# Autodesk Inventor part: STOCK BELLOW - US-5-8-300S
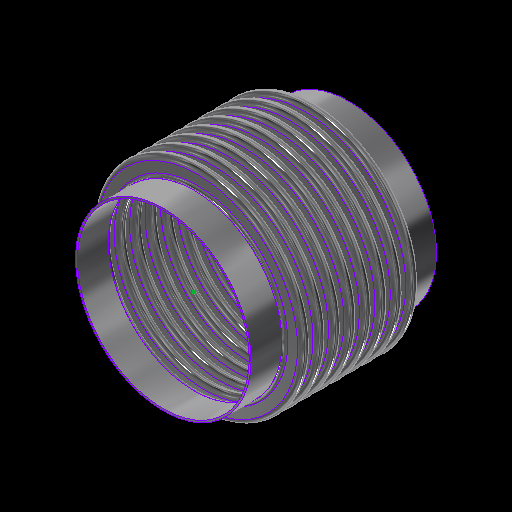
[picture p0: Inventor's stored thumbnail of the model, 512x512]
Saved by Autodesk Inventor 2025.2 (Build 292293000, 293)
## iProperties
Category: 22 GA (0.030 THICK)
RuleStatus: InUse
Created: 2024-01
Part Number: STOCK BELLOW - US-5-8-300S
Project: =STOCK BELLOWS: <Stock Number><SFILL>
Material: ASTM A240-304
Description: =STOCK BELLOWS: <Stock Number>, <SID_> I.D., <SOD_> O.D., <SPLY_> PLY, <Category>, <SNET_CONS> CONS.<PITCH_><STANGENT_> TANGENT<SFILL>
Document SubType Name: Sheet Metal
Designer: GS
Stock Number: U.S-5-8-300S
Surface Area: 3335.57 cm^2
Volume: 251.046 cm^3
Sheet Metal Rule: Default
Appearance: STAINLESS STEEL
Mass: 2022.75 g
Density: 8.05729 g/cm^3
THK: 0.036
ID: 3.500
OD: 4.250
CONS_: 2
PITCH: 0.500
TANGENT: 0.500
BELLOWS_UPSET: 0.000
d79: 1.000
d82: 1.000
d83: 26.000
d84: 24.000
d174: 8
d214: 8
STHK_: 0.030
SID_: 5.560
SOD_: 6.810
SPITCH_: 0.500
STANGENT__: 1.000
SBELLOWS_UPSET_: 0.000
SDIFF_TAN: 1.000
d252: 2
d275: 2
d287: 0.050
d289: 0.500
d290: 0.000
SOD_NECK: 5 11/16
PLY: 1
PSET: 4.178
PBAR: 1.035
COUNTER: 1.500
NET_TUBE: 3.071
CONS: 2
S_CONS: 0
NET_CONS: 2
ID_M: 88.90 mm
OD_M: 107.95 mm
THK_M: 0.91 mm
ID_U: 3.500 in
OD_U: 4.250 in
THK_U: 0.036 in
TANGENT2: 0.500
TAN_TO_TAN: 1.000 in
d80: 2.571
d81: 10
SID: 2.375
SCONS_: 8
SPITCH: 0.250
STANGENT_: 1.000
SBELLOWS_UPSET: 0.000
SNET_CONS: 8
SS_CONS: 0
SCONS: 8
d190: 8
d191: 1
d192: 1
d193: 8
d194: 0
SIZE: 5.00
PRESSURE: 300
d230: 8
STANGENT: 4.000
SPLY_: 2
d233: 8
d234: 0
d263: 2
d265: 1
d268: 2
d269: 0
d286: 2
d288: 1
d291: 2
d292: 0
SREROLL: 0.750
BLETP: 0.000 ul
PRES_Copy: 85
MATTABLE: 20 GA (0.036 THICK)
PART_NUMBER: U.S-5-8-300S
PITCH_: =, <SPITCH_> PITCH,
CFILL: .
SFILL: .
MESH: ,
COMP: 0.74
EXT: 0.37
LAT: 0.16
ANG: 573
ASR: 3217
LSR: 11536
ANSR: 268
PRES: 300
COMPM: 7.4
EXTM: 3.7
LATM: 1.60
ASRM: 563.393
PRESM: 20.684
LSRM: 2020.300
ANSRM: 46.935
TEMPMIN: 20
TEMPMAX: 800
TEMPMINM: -7
TEMPMAXM: 427
WEIGHTM: 2.023
WEIGHT: 4.459
Author: GS
Keywords: 20 GA (0.036 THICK)
Comments: =STOCK BELLOW - <STOCK NUMBER>
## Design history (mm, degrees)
sketch "Sketch2"
  geometry: L1 (0, -177.245)-(0, 562.856) reference; L2 (45.364, 0)-(44.45, 0); L3 (48.082, -2.718)-(50.343, -2.718); L4 (48.082, -3.632)-(50.343, -3.632); L5 (50.343, -9.982)-(48.082, -9.982); L6 (50.343, -9.068)-(48.082, -9.068); L7 (45.364, -12.7)-(44.45, -12.7); L8 (48.082, 0)-(48.082, -12.7); L9 (50.343, -6.35)-(53.975, -6.35); L10 (44.45, 0)-(44.45, -12.7); L11 (20.376, 102.841)-(20.376, 101.926); L12 (58.262, 457.127)-(58.262, 349.177); L13 (58.262, 444.427)-(58.262, 336.477); L14 (93.133, -58.817)-(93.133, -71.517); L15 (118.746, -66.401)-(118.746, -66.401); L16 (50.343, -9.068)-(50.343, -9.982); L17 (48.082, -9.068)-(48.082, -9.982); L18 (48.082, -9.525)-(50.343, -9.525); L19 (53.975, 0)-(53.975, -12.7); L20 (-50.343, -9.068)-(-50.343, -9.982); L21 (-50.343, -2.718)-(-48.082, -2.718); L22 (-50.343, -3.632)-(-48.082, -3.632); L23 (-48.082, -9.068)-(-50.343, -9.068); L24 (-50.343, -9.525)-(-48.082, -9.525); L25 (-48.082, -9.982)-(-50.343, -9.982); L26 (-48.082, -9.068)-(-48.082, -9.982); L27 (-44.45, 0.653)-(-44.45, -12.047); L28 (-48.082, -6.35)-(-44.45, -6.35); L29 (-50.343, 0.653)-(-50.343, -12.7); L30 (-53.061, 0)-(-53.975, 0); L31 (-53.975, 0)-(-53.975, -12.7); L32 (-53.061, -12.7)-(-53.975, -12.7); A1 r 2.718 centre (48.082, 0) between (45.364, 0) and (48.082, -2.718); A2 r 3.632 centre (48.082, 0) between (44.45, 0) and (48.082, -3.632); A3 r 3.632 centre (50.343, -6.35) between (50.343, -9.982) and (50.343, -2.718); A4 r 2.718 centre (50.343, -6.35) between (50.343, -9.068) and (50.343, -3.632); A5 r 2.718 centre (48.082, -12.7) between (48.082, -9.982) and (45.364, -12.7); A6 r 3.632 centre (48.082, -12.7) between (48.082, -9.068) and (44.45, -12.7); A7 r 3.175 centre (50.343, -6.35) between (50.343, -9.525) and (53.518, -6.35); A8 r 3.175 centre (48.082, -12.7) between (48.082, -9.525) and (44.907, -12.7); A9 r 2.718 centre (-50.343, -12.7) between (-50.343, -9.982) and (-53.061, -12.7); A10 r 2.718 centre (-48.082, -6.35) between (-48.082, -9.068) and (-48.082, -3.632); A11 r 3.175 centre (-48.082, -6.35) between (-48.082, -9.525) and (-44.907, -6.35); A12 r 3.632 centre (-48.082, -6.35) between (-48.082, -9.982) and (-48.082, -2.718); A13 r 3.175 centre (-50.343, -12.7) between (-50.343, -9.525) and (-53.518, -12.7); A14 r 3.632 centre (-50.343, -12.7) between (-50.343, -9.068) and (-53.975, -12.7); A15 r 2.718 centre (-50.343, 0) between (-53.061, 0) and (-50.343, -2.718); A16 r 3.632 centre (-50.343, 0) between (-53.975, 0) and (-50.343, -3.632); 10 further points
  constraints: 62 end point, 38 point on circle, 20 tangent, 16 centre point, 12 parallel, 9 midpoint, 7 vertical, 6 coincident, 6 concentric, 6 point on line, 4 equal radius, 4 perpendicular, 3 horizontal, 1 collinear, 1 horizontal alignment, 10 other
  dimensions: "THK" = 0.9144 distance of L11.start L11.end; "ID" = 88.9 distance of L11.end point (20.376, 13.026); "OD" = 107.95 distance of L12.start L12.end; "PITCH" = 12.7 distance of L12.start L13.start; "TANGENT" = 12.7 distance of L14.start L14.end; "BELLOWS_UPSET" = 0 distance of L15.start L15.end; "d43" = 88.9 diameter of L10 L1 (= ID); "d44" = 107.95 diameter of L9.end L1 (= OD); "d45" = 0.9144 distance between parallel lines of L5 L6 (computed from THK, PLY); "d46" = 3.6322 radius of A3 (computed from PITCH, THK, PLY); "UPSET_PITCH" = 12.7 distance of L2.end L7.end (derived); "SIDEWALL_ANGLE" = 360 deg dimension on L3 L9 (derived); "CON_GAP" = 5.4356 distance of point (48.082, -9.068) point (48.082, -3.632) (derived); "TAN1" = 4.98728 dimension on A8 (derived); "TAN2" = 4.98728 dimension on A7 (derived); "LEG1" = 2.2606 distance of L18.start L18.end (derived); "d278" = 0.9144 distance between parallel lines of L25 L23 (derived); "d279" = 3.6322 radius of A12 (derived); "d280" = 12.7 distance of L30.end L31.end (derived); "d281" = 360 deg dimension on L21 L28 (derived); "d282" = 5.4356 distance of point (-50.343, -9.068) point (-50.343, -3.632) (derived); "d283" = 4.98728 dimension on A13 (derived); "d284" = 4.98728 dimension on A11 (derived); "d285" = 2.2606 distance of L24.start L24.end (derived); "d293" = 88.9 diameter of L27 L1 (derived); "d294" = 107.95 diameter of L31 L1 (derived)
  node "Sketch Rectangular Pattern1" dims "d31" = 25.4, "ID" = 88.9
  node "Sketch Rectangular Pattern2" dims "d39" = 25.4, "PITCH" = 12.7
revolve "CONS" stored, may be unused: angle "d48" = 90 deg
node "BELLOW MIDPLANE"
pattern_linear "Rectangular Pattern2" dims "d52" = 12.7 (= UPSET_PITCH)
sketch "Sketch5"
  geometry: C1 r 45.364 at (0, 0) reference; C2 r 44.45 at (0, 0) reference
extrude "TANGENT" new body sketch "Sketch5" distance "d53" = 12.7 (= TANGENT); taper "d54" = 0 deg
revolve "SAMETAN" stored, may be unused: angle "d65" = 90 deg
revolve "DIFFTAN" stored, may be unused: angle "d70" = 90 deg
sketch "Sketch9"
  geometry: L1 (53.319, 0)-(-53.319, 0) reference; L2 (0, -17.78)-(0, 17.78) reference; L3 (38.085, 0)-(-38.085, 0); L4 (38.085, -11.906)-(38.085, 11.906); L5 (25.385, -11.906)-(25.385, 11.906); L6 (13.15, 11.906)-(13.15, -11.906); L7 (-25.385, -11.906)-(-25.385, 11.906); L8 (-38.085, -11.906)-(-38.085, 11.906); L9 (37.291, -11.906)-(37.291, 11.906); L10 (38.085, -11.906)-(37.291, -11.906); L11 (38.085, 11.906)-(37.291, 11.906); L12 (13.546, 11.906)-(12.753, 11.906); L13 (12.753, 11.906)-(12.753, -11.906); L14 (12.753, -11.906)-(13.546, -11.906); L15 (13.546, -11.906)-(13.546, 11.906); L16 (-13.546, 11.906)-(-13.546, -11.906); L17 (-13.15, 11.906)-(-13.15, -11.906); L18 (-13.546, -11.906)-(-12.753, -11.906); L19 (-12.753, -11.906)-(-12.753, 11.906); L20 (-12.753, 11.906)-(-13.546, 11.906); L21 (-38.085, -11.906)-(-37.291, -11.906); L22 (-37.291, -11.906)-(-37.291, 11.906); L23 (-37.291, 11.906)-(-38.085, 11.906); L24 (-38.085, 11.906)-(-38.085, -11.906); L25 (38.085, -0.397)-(-38.085, -0.397); L26 (-38.085, -0.397)-(-38.085, 0.397); L27 (-38.085, 0.397)-(38.085, 0.397); L28 (38.085, 0.397)-(38.085, -0.397); L29 (-38.085, 11.906)-(38.085, 11.906); L30 (38.085, 11.906)-(38.085, 12.7); L31 (38.085, 12.7)-(-38.085, 12.7); L32 (-38.085, 12.7)-(-38.085, 11.906); L33 (38.085, -11.906)-(-38.085, -11.906); L34 (-38.085, -11.906)-(-38.085, -12.7); L35 (-38.085, -12.7)-(38.085, -12.7); L36 (38.085, -12.7)-(38.085, -11.906); 30 further points
  constraints: 68 end point, 13 midpoint, 13 parallel, 8 horizontal, 7 perpendicular, 6 equal length, 3 point on line, 2 vertical, 14 other
  dimensions: "d115" = 23.8125 distance of L4.start L4.end (derived); "d116" = 12.7 distance between parallel lines of L4 L5 (derived); "d117" = 12.23516 distance between parallel lines of L5 L6 (derived); "d125" = 38.53427 distance between parallel lines of L7 L6 (derived); "d127" = 12.7 distance between parallel lines of L8 L7 (derived); "d128" = 24.93516 distance between parallel lines of L6 L4 (derived); "d130" = 76.16943 distance between parallel lines of L8 L4 (derived); "RULER_THK" = 0.79375 distance between parallel lines of L4 L9; "d135" = 0.79375 distance of L13.end L14.end (derived); "d138" = 26.29911 distance of L13.end L16.end (derived); "d143" = 0.79375 distance of L22.end L8.end (derived); "d144" = 0.79375 distance between parallel lines of L27 L25 (derived)
extrude "RULER" join sketch "Sketch9" distance "d149" = 0.79375 (derived); taper "d150" = 0 deg
extrude "BARS" join sketch "Sketch9" distance "d151" = 0.79375 (derived); taper "d152" = 0 deg
pattern_linear "Rectangular Pattern4" dims "d155" = 26.29911 (derived)
sketch "Sketch13"
  geometry: L1 (93.149, -52.467)-(93.149, -77.867); L2 (72.136, 0)-(70.612, 0); L3 (72.136, -12.7)-(70.612, -12.7); L4 (82.55, -10.287)-(74.549, -10.287); L5 (82.55, -8.763)-(74.549, -8.763); L6 (82.55, -6.35)-(86.487, -6.35); L7 (74.549, -2.413)-(82.55, -2.413); L8 (74.549, 0)-(74.549, -12.7); L9 (70.612, 0)-(70.612, -12.7); L10 (58.254, -323.457)-(58.254, -496.431); L11 (58.254, -336.157)-(58.254, -509.131); L12 (58.254, -361.557)-(58.254, -534.531); L13 (58.254, -374.257)-(58.254, -547.231); L14 (58.254, -386.957)-(58.254, -559.931); L15 (58.254, -399.657)-(58.254, -572.631); L16 (58.254, -412.357)-(58.254, -585.331); L17 (58.254, -348.857)-(58.254, -521.831); L18 (20.376, 102.688)-(20.376, 101.926); L19 (74.549, -3.937)-(82.55, -3.937); L20 (0, -722.935)-(0, 240.292) reference; L21 (-23.752, 0)-(142.514, 0) reference; A1 r 2.413 centre (74.549, 0) between (72.136, 0) and (74.549, -2.413); A2 r 2.413 centre (74.549, -12.7) between (74.549, -10.287) and (72.136, -12.7); A3 r 3.937 centre (74.549, -12.7) between (74.549, -8.763) and (70.612, -12.7); A4 r 2.413 centre (82.55, -6.35) between (82.55, -8.763) and (82.55, -3.937); A5 r 3.937 centre (82.55, -6.35) between (82.55, -10.287) and (82.55, -2.413); A6 r 3.937 centre (74.549, 0) between (70.612, 0) and (74.549, -3.937); 6 further points; 1 other entity
  constraints: 38 end point, 15 point on circle, 9 tangent, 6 centre point, 6 parallel, 5 vertical alignment, 4 point on line, 4 vertical, 3 coincident, 3 concentric, 2 collinear, 2 equal radius, 1 horizontal, 1 perpendicular, 23 other
  dimensions: "SBELLOWS_UPSET_" = 0 distance of point (118.762, -66.401) point (118.762, -66.401); "STOTAL_THK_BELLOW__" = 1.524 distance between parallel lines of L4 L5 (derived); "d224" = 3.937 radius of A5 (derived); "d225" = 12.7 distance of L2.end L3.end (derived); "SSIDEWALL_ANGLE_" = 360 deg dimension on L7 L6 (derived); "SSCON_GAP_" = 4.826 distance of point (74.549, -8.763) point (74.549, -3.937) (derived); "d235" = 141.224 diameter of L9 L20 (derived); "d236" = 172.974 diameter of L6.end L20 (derived)
  node "Sketch Rectangular Pattern4" dims "d228" = 25.4
  node "Sketch Rectangular Pattern5" dims "d229" = 25.4
revolve "SBELLOW" stored, may be unused: angle "d197" = 90 deg
pattern_linear "Rectangular Pattern5" dims "d204" = 12.7 (derived)
revolve "STANGENT" stored, may be unused: angle "d240" = 90 deg
revolve "SSAMETAN" stored, may be unused: angle "d241" = 90 deg
revolve "SDIFFTAN" stored, may be unused: angle "d246" = 90 deg
revolve "INVCON" stored, may be unused: angle "d295" = 90 deg
pattern_linear "Rectangular Pattern6" dims "d298" = 12.7 (derived)
revolve "INVTANGENT" stored, may be unused: angle "d302" = 90 deg
revolve "INVSAMETAN" stored, may be unused: angle "d307" = 90 deg
revolve "INVDIFFTAN" stored, may be unused: angle "d312" = 90 deg
sketch "ID BELLOW MOUNT CALC"
  geometry: L1 (44.45, 0)-(38.1, 0); L2 (38.1, 0)-(38.1, 12.7); L3 (38.1, 12.7)-(44.45, 12.7); L4 (44.45, 12.7)-(44.45, 0); L5 (36.513, 12.7)-(35.598, 12.7); L6 (35.598, 12.7)-(35.598, 0); L7 (35.598, 0)-(36.513, 0); L8 (36.513, 0)-(36.513, 12.7); L9 (0, -2.54)-(0, 15.24) reference; L10 (-8.89, 0)-(53.34, 0) reference; 1 further point
  constraints: 16 end point, 5 parallel, 2 collinear, 2 horizontal, 2 perpendicular
  dimensions: "d314" = 12.7 distance of L5.end L6.end (derived); "d315" = 0.9144 distance of L5.start L5.end (derived); "IG" = 1.5875 distance between parallel lines of L2 L8; "PIPE_OD" = 88.9 diameter of L4 L9; "PIPE_WALL" = 6.35 distance of L2.end L3.end; "ID_MT_BELLOW" = 71.1962 diameter of L6 L9 (derived)
revolve "CFILL" stored, may be unused: angle "d320" = 90 deg
pattern_linear "Rectangular Pattern7" dims "d323" = 12.7 (derived)
revolve "SFILL" stored, may be unused: angle "d324" = 90 deg
pattern_linear "Rectangular Pattern8" dims "d327" = 12.7 (derived)
node "STOCK BELLOW MIDPLANE"
node "BELLOW"
sketch "Sketch6"
  geometry: L1 (-12.7, 45.364)-(0, 45.364); L2 (0, 45.364)-(0, 44.45); L3 (0, 44.45)-(-12.7, 44.45); L4 (-12.7, 44.45)-(-12.7, 45.364); L5 (10.16, 0)-(-60.96, 0) reference; L6 (-38.1, -89.422)-(-38.1, 153.44) reference; 1 further point
  constraints: 8 end point, 2 parallel, 1 horizontal, 1 perpendicular
  dimensions: "d61" = 12.7 distance of L2.end L3.end (derived); "d62" = 0.9144 distance of L1.end L2.end (derived); "d63" = 88.9 diameter of L3 L5 (derived); "d64" = 25.4 distance between parallel lines of L4 L6 (derived)
sketch "Sketch12"
  geometry: 1 further point
sketch "Sketch14"
  geometry: L1 (-25.4, 72.136)-(0, 72.136); L2 (0, 72.136)-(0, 70.612); L3 (0, 70.612)-(-25.4, 70.612); L4 (-25.4, 70.612)-(-25.4, 72.136); L5 (5.08, 0)-(-30.48, 0) reference; L6 (0, -14.427)-(0, 86.563) reference; 1 further point
  constraints: 8 end point, 2 parallel, 1 collinear, 1 horizontal, 1 perpendicular
  dimensions: "d237" = 1.524 distance of L3.end L1.start (derived); "d238" = 141.224 diameter of L3 L5 (derived); "d239" = 25.4 distance of L1.start L1.end (derived); "SOD_NECK" = 144.272 diameter of L1 L5 (derived)
sketch "Sketch15"
  geometry: L1 (-14.427, 0)-(86.563, 0) reference; L2 (70.612, -101.6)-(72.136, -101.6); L3 (72.136, -101.6)-(72.136, -127); L4 (72.136, -127)-(70.612, -127); L5 (70.612, -127)-(70.612, -101.6); L6 (0, -154.94)-(0, 40.64) reference; 1 further point
  constraints: 8 end point, 2 parallel, 1 horizontal, 1 perpendicular
  dimensions: "d205" = 25.4 distance of L4.end L2.start (derived); "d206" = 1.524 distance of L3.end L4.end (derived); "d207" = 141.224 diameter of L5 L6 (derived); "d208" = 101.6 distance between parallel lines of L1 L2 (derived)
node "TANGENT_"
node "SAME_TAN"
sketch "Sketch8"
  geometry: L1 (45.364, -25.4)-(44.45, -25.4); L2 (44.45, -25.4)-(44.45, -38.1); L3 (44.45, -38.1)-(45.364, -38.1); L4 (45.364, -38.1)-(45.364, -25.4); L5 (0, -48.26)-(0, 22.86) reference; L6 (-89.422, 0)-(153.44, 0) reference; 1 further point
  constraints: 8 end point, 2 parallel, 1 horizontal, 1 perpendicular
  dimensions: "d66" = 88.9 diameter of L2 L5 (derived); "TOTAL_THK_BELLOW" = 0.9144 distance of L2.end L3.end (derived); "d68" = 25.4 distance between parallel lines of L1 L6 (derived); "d69" = 12.7 distance of L1.end L2.end (derived)
node "DIFF_TAN"
node "Sketch Rectangular Pattern3" dims "d138" = 26.29911 (derived), "d141" = 25.4
node "SBELLOW_"
node "STANGENT_"
node "SSAME_TAN"
sketch "Sketch16"
  geometry: L1 (72.136, -101.6)-(70.612, -101.6); L2 (70.612, -101.6)-(70.612, -127); L3 (70.612, -127)-(72.136, -127); L4 (72.136, -127)-(72.136, -101.6); L5 (0, -154.94)-(0, 40.64) reference; L6 (-14.427, 0)-(86.563, 0) reference; 1 further point
  constraints: 8 end point, 2 parallel, 1 horizontal, 1 perpendicular
  dimensions: "SDIFF_TAN" = 25.4 distance of L3.end L1.start; "d243" = 1.524 distance of L2.end L3.end (derived); "d244" = 101.6 distance between parallel lines of L1 L6 (derived); "d245" = 141.224 diameter of L2 L5 (derived)
node "SDIFF_TAN"
body "Solid15"
sketch "Sketch17"
  geometry: L1 (53.975, 12.7)-(53.061, 12.7); L2 (53.061, 12.7)-(53.061, 0); L3 (53.061, 0)-(53.975, 0); L4 (53.975, 0)-(53.975, 12.7); L5 (0, -2.54)-(0, 15.24) reference; L6 (-10.795, 0)-(64.77, 0) reference; 2 further points
  constraints: 8 end point, 2 parallel, 1 horizontal, 1 midpoint, 1 perpendicular, 1 point on line
  dimensions: "INVTANGENT" = 12.7 distance of L3.end L1.start (derived); "d300" = 0.9144 distance of L1.start L1.end (derived); "d301" = 107.95 diameter of L4 L5 (derived)
body "Solid16"
sketch "Sketch18"
  geometry: L1 (53.975, -25.4)-(53.061, -25.4); L2 (53.061, -25.4)-(53.061, -38.1); L3 (53.061, -38.1)-(53.975, -38.1); L4 (53.975, -38.1)-(53.975, -25.4); L5 (-10.795, 0)-(64.77, 0) reference; L6 (0, -48.26)-(0, 22.86) reference; 1 further point
  constraints: 8 end point, 2 parallel, 1 horizontal, 1 perpendicular
  dimensions: "d303" = 25.4 distance between parallel lines of L1 L5 (derived); "d304" = 12.7 distance of L3.end L1.start (derived); "d305" = 0.9144 distance of L2.end L3.end (derived); "d306" = 107.95 diameter of L4 L6 (derived)
body "Solid17"
sketch "Sketch19"
  geometry: L1 (53.975, -25.4)-(53.061, -25.4); L2 (53.061, -25.4)-(53.061, -38.1); L3 (53.061, -38.1)-(53.975, -38.1); L4 (53.975, -38.1)-(53.975, -25.4); L5 (0, -48.26)-(0, 22.86) reference; L6 (-10.795, 0)-(64.77, 0) reference; 1 further point
  constraints: 8 end point, 2 parallel, 1 horizontal, 1 perpendicular
  dimensions: "d308" = 12.7 distance of L1.end L2.end (derived); "d309" = 107.95 diameter of L4 L5 (derived); "d310" = 0.9144 distance of L2.end L3.end (derived); "d311" = 25.4 distance between parallel lines of L1 L6 (derived)
body "Solid18"
body "Solid19"
body "Solid20"
other parameters: "BMPL" = -50.8, "PSET" = 106.1212 (computed from OD, THK, PLY) [user parameter], "PBAR" = 26.29911 (= 0.570796 x PITCH + OD - ID) [user parameter; used in 1 equation term], "COUNTER" = 15 [user parameter], "NET_TUBE" = 77.99823 (computed from CONS_, PBAR, TANGENT) [user parameter], "S_CONS" = 0 [user parameter; used in 1 equation term], "ID_M" = 88.9 (= ID) [user parameter], "OD_M" = 107.95 (= OD) [user parameter], "THK_M" = 0.9144 (= THK) [user parameter], "ID_U" = 88.9 (= ID) [user parameter], "OD_U" = 107.95 (= OD) [user parameter], "THK_U" = 0.9144 (= THK) [user parameter], "D_UNITS" = 0 [user parameter], "TANGENT2" = 12.7 [user parameter], "TAN_TO_TAN" = 25.4 [user parameter], "OD_NECK" = 90.7288 [user parameter], "d79" = 25.4, "d80" = 65.29823 [user parameter], "d82" = 25.4, "d83" = 660.4, "d84" = 609.6, "sa_0" = 4, "FRAME_THK" = 0.79375 [user parameter], "CON_FLAT" = 12.23516 [user parameter], "SID" = 60.325 [user parameter], "SPITCH" = 6.35 [user parameter], "STANGENT_" = 25.4 [user parameter], "SBELLOWS_UPSET" = 0 [user parameter], "SS_CONS" = 0 [user parameter], "STAN_TO_TAN_" = 101.6 [user parameter], "d100" = 1.524 [user parameter], "d191" = 25.4 [user parameter], "d194" = 0 [user parameter], "STANGENT" = 101.6 [user parameter], "d234" = 0 [user parameter], "SUPSET_PITCH_" = 12.7 [user parameter], "d269" = 0 [user parameter], "d287" = 1.27, "d289" = 12.7, "d290" = 0, "d292" = 0 [user parameter], "Thickness" = 3.048 (derived), "KFactor" = 4.4, "BendRadius" = 3.048 (derived), "BendReliefWidth" = 3.048 (derived), "BendReliefDepth" = 1.524 (derived), "CornerReliefSize" = 12.192 (derived), "SeamGap" = 0.00508, "MinimumRemnant" = 6.096 (derived), "TransitionRadius" = 3.048 (derived), "JacobiRadiusSize" = 3.048 (derived), "GapSize" = 3.048 (derived), "SREROLL" = 19.05 [user parameter], "CUR_STK_PITCH" = 12.7 [user parameter], "d328" = -50.8 (derived), "ASR" = 32170 [user parameter], "LSR" = 115360 [user parameter], "BLETP" = 0 [user parameter], "ASRM" = 5633.9321 [user parameter], "PRESM" = 206.83949 [user parameter], "LSRM" = 20202.9968 [user parameter], "ANSRM" = 469.3484 [user parameter], "TEMPMIN" = 2664.83333 [user parameter], "TEMPMAX" = 6998.16667 [user parameter], "TEMPMINM" = 2664.83333 [user parameter], "TEMPMAXM" = 6998.16667 [user parameter], "WEIGHT" = 20.2275 [user parameter], "WEIGHTM" = 0.02023 [user parameter]
